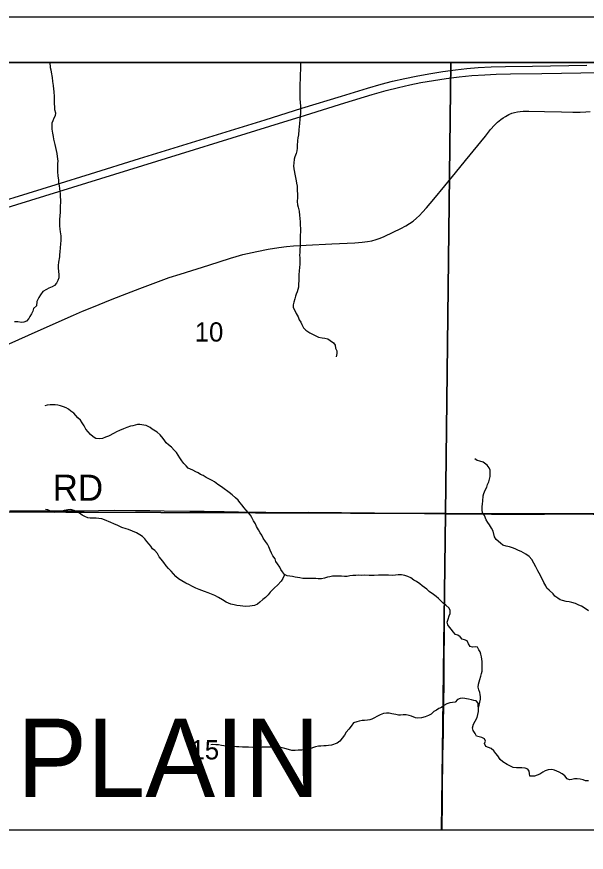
# Model space of a CAD drawing. Extents: x 0 to 34, y 0 to 22.
# Drawn here: x 2.711 to 3.95, y 19.182 to 21 of the extents above; entities that cross this region are included whole.
import ezdxf

# ---------------------------------------------------------------- set-up
doc = ezdxf.new("R2010")
doc.units = 0
for name, color, linetype in [('Default', 7, 'Continuous'), ('GM_X_County_Road', 7, 'Continuous'), ('GM_X_County_Road_Text', 7, 'Continuous'), ('GM_X_Minor_River', 7, 'Continuous'), ('GM_X_Section', 7, 'Continuous'), ('GM_X_Section_Text', 7, 'Continuous'), ('GM_X_State_Route', 7, 'Continuous'), ('GM_X_Township_Road', 7, 'Continuous'), ('GM_X_Township_Text', 7, 'Continuous'), ('GM_X_US_Route', 7, 'Continuous'), ('SH_Data', 7, 'Continuous'), ('SH_Text', 7, 'Continuous')]:
    doc.layers.add(name, color=color, linetype=linetype)

msp = doc.modelspace()

# ---------------------------------------------------------------- linework, layer by layer
at = {"layer": 'Default'}
for points in [[(3.6554, 20.9), (2.6196, 20.9), (2.6102, 19.9231), (3.6434, 19.919)], [(4.655, 20.9), (3.6554, 20.9), (3.6434, 19.919), (4.6576, 19.9182)]]:
    msp.add_lwpolyline(points, close=True, dxfattribs=at)
at = {"layer": 'GM_X_County_Road'}
for points in [[(2.6611, 20.274), (2.7153, 20.298), (2.7578, 20.3168), (2.8346, 20.3505), (2.8542, 20.359), (2.8777, 20.3686), (2.915, 20.3837), (2.9413, 20.3939), (2.9789, 20.4085), (3.0193, 20.424), (3.0312, 20.4284), (3.0426, 20.4323), (3.0665, 20.4397), (3.1285, 20.4596), (3.1761, 20.475), (3.1879, 20.4784), (3.2029, 20.4824), (3.2333, 20.489), (3.2576, 20.494), (3.2813, 20.498), (3.2975, 20.5002), (3.3129, 20.5018), (3.3408, 20.5033), (3.3966, 20.5059), (3.4464, 20.5083), (3.4619, 20.5095), (3.4742, 20.511), (3.4834, 20.5127), (3.4927, 20.515), (3.5015, 20.518), (3.5101, 20.5217), (3.5299, 20.5311), (3.5464, 20.5394), (3.5573, 20.5453), (3.5654, 20.5504), (3.5729, 20.5555), (3.5803, 20.5614), (3.5872, 20.5677), (3.5936, 20.5745), (3.602, 20.5838), (3.6178, 20.6029), (3.6418, 20.6318), (3.6654, 20.6606), (3.6869, 20.6872), (3.7301, 20.7403), (3.7416, 20.7544), (3.75, 20.7638), (3.7565, 20.7704), (3.7636, 20.7763), (3.7688, 20.7799), (3.774, 20.7832), (3.7814, 20.7872), (3.7879, 20.7898), (3.7938, 20.7916), (3.7997, 20.793), (3.8058, 20.7939), (3.812, 20.7944), (3.8243, 20.7945), (3.8585, 20.7938), (3.8957, 20.7927), (3.9204, 20.792), (3.9361, 20.7921), (3.9486, 20.7929), (3.9578, 20.7941)], [(2.6962, 19.9254), (2.7149, 19.9253), (2.7397, 19.9253), (2.7708, 19.9253), (2.805, 19.9251), (2.8578, 19.9251), (2.8889, 19.9257), (2.9231, 19.9261), (2.9697, 19.926), (3.0008, 19.9255), (3.0319, 19.925), (3.0878, 19.9244), (3.1189, 19.924), (3.1622, 19.9237), (3.1936, 19.9231), (3.2245, 19.9223), (3.2525, 19.9218), (3.296, 19.9217), (3.3457, 19.9218), (3.3986, 19.9215), (3.4172, 19.9213), (3.4638, 19.9209), (3.4887, 19.9207), (3.5291, 19.9202), (3.5602, 19.9198), (3.5975, 19.9194), (3.6444, 19.9187)], [(3.6444, 19.9187), (3.6472, 19.9187), (3.6814, 19.9184), (3.7001, 19.9183), (3.7249, 19.9182), (3.7435, 19.918), (3.7715, 19.9177), (3.8026, 19.9179), (3.8585, 19.9179), (3.9207, 19.9181), (3.9393, 19.9181), (3.9642, 19.918), (4.0046, 19.9179), (4.0419, 19.9177), (4.1527, 19.9174)]]:
    msp.add_lwpolyline(points, dxfattribs=at)
at = {"layer": 'GM_X_Minor_River'}
for points in [[(2.7828, 20.9), (2.7839, 20.8897), (2.7851, 20.8847), (2.7859, 20.879), (2.7879, 20.868), (2.789, 20.8589), (2.7902, 20.8505), (2.791, 20.8426), (2.7918, 20.8369), (2.7923, 20.8258), (2.7923, 20.8171), (2.7923, 20.811), (2.7931, 20.803), (2.7935, 20.7981), (2.7955, 20.7909), (2.7944, 20.7844), (2.7921, 20.7791), (2.7895, 20.7737), (2.7876, 20.768), (2.7873, 20.76), (2.7877, 20.7551), (2.7889, 20.7467), (2.7904, 20.7391), (2.7912, 20.7338), (2.7928, 20.7277), (2.7939, 20.7221), (2.797, 20.7091), (2.7982, 20.7023), (2.799, 20.6962), (2.7998, 20.6909), (2.8002, 20.686), (2.7998, 20.6803), (2.7999, 20.67), (2.7996, 20.6635), (2.8007, 20.6529), (2.8016, 20.6449), (2.802, 20.6384), (2.8031, 20.6331), (2.8043, 20.6255), (2.8047, 20.6206), (2.8055, 20.6145), (2.8055, 20.608), (2.806, 20.6016), (2.806, 20.5955), (2.8056, 20.5887), (2.8057, 20.5746), (2.805, 20.567), (2.8043, 20.5586), (2.8044, 20.5453), (2.8051, 20.5377), (2.8059, 20.532), (2.8067, 20.5233), (2.8068, 20.5141), (2.8061, 20.505), (2.8057, 20.4978), (2.805, 20.4879), (2.8043, 20.4829), (2.8043, 20.4776), (2.8017, 20.4662), (2.801, 20.4586), (2.801, 20.4529), (2.8018, 20.4464), (2.8026, 20.4385), (2.8023, 20.432), (2.8008, 20.4259), (2.7978, 20.4206), (2.7929, 20.4152), (2.788, 20.4125), (2.7808, 20.4095), (2.7755, 20.4064), (2.7679, 20.4022), (2.7626, 20.3949), (2.7589, 20.3888), (2.7551, 20.3801), (2.7544, 20.3713), (2.7472, 20.3648), (2.7461, 20.3595), (2.7435, 20.3534), (2.7397, 20.3481), (2.7375, 20.3431), (2.7326, 20.3374), (2.7265, 20.3351), (2.7212, 20.3347), (2.7132, 20.3358), (2.7064, 20.3361)], [(3.3287, 20.9), (3.3285, 20.8979), (3.3278, 20.891), (3.3278, 20.8827), (3.3275, 20.8773), (3.3272, 20.8674), (3.3272, 20.8617), (3.3268, 20.8564), (3.327, 20.823), (3.3275, 20.8119), (3.3279, 20.807), (3.3279, 20.7918), (3.3272, 20.7823), (3.3269, 20.777), (3.3258, 20.7671), (3.3251, 20.761), (3.3247, 20.7541), (3.3236, 20.7427), (3.3225, 20.7366), (3.3218, 20.7309), (3.3207, 20.7191), (3.3208, 20.7142), (3.32, 20.7081), (3.3189, 20.7024), (3.3155, 20.6952), (3.3144, 20.6902), (3.3133, 20.6815), (3.3126, 20.6758), (3.3138, 20.6693), (3.3169, 20.6541), (3.3185, 20.6431), (3.3193, 20.6378), (3.3208, 20.6313), (3.3212, 20.6203), (3.3217, 20.615), (3.3217, 20.607), (3.321, 20.5978), (3.3218, 20.591), (3.3229, 20.5853), (3.3253, 20.5766)], [(3.3253, 20.5766), (3.3261, 20.5675), (3.3269, 20.5618), (3.3273, 20.553), (3.3277, 20.5462), (3.3281, 20.5389), (3.3282, 20.531), (3.3274, 20.5253), (3.3271, 20.5142), (3.3272, 20.5005), (3.3268, 20.4945), (3.3265, 20.4872), (3.3261, 20.4815), (3.3266, 20.4754), (3.327, 20.4678), (3.3266, 20.4606), (3.3259, 20.4553), (3.3252, 20.4465), (3.3245, 20.4393), (3.3245, 20.4317), (3.3242, 20.4268), (3.3238, 20.4173), (3.3239, 20.4116), (3.3209, 20.4017), (3.319, 20.3967), (3.3175, 20.3918), (3.3156, 20.3864), (3.3138, 20.3788), (3.3119, 20.3731), (3.3119, 20.367), (3.3162, 20.3591), (3.3185, 20.3541), (3.3231, 20.3469), (3.3254, 20.3408), (3.3292, 20.3352), (3.3307, 20.3302), (3.3346, 20.323), (3.3399, 20.3177), (3.3483, 20.3124), (3.3673, 20.303), (3.3749, 20.3012), (3.3814, 20.3008), (3.3874, 20.2993), (3.3924, 20.2959), (3.3996, 20.2902), (3.4038, 20.2853), (3.4046, 20.2785), (3.4069, 20.2728), (3.4074, 20.2675), (3.4055, 20.2602)], [(3.2727, 19.8209), (3.2677, 19.8273), (3.265, 19.833), (3.2623, 19.8394), (3.2593, 19.847), (3.2566, 19.8523), (3.2524, 19.858), (3.2467, 19.8656), (3.244, 19.8717), (3.2405, 19.877), (3.2367, 19.8834), (3.2325, 19.891), (3.2302, 19.8967), (3.2263, 19.9035), (3.2221, 19.9104), (3.2191, 19.9153), (3.2099, 19.9266), (3.2049, 19.9323), (3.2011, 19.9376), (3.1961, 19.9433), (3.1923, 19.9482), (3.1866, 19.9535), (3.1797, 19.9596), (3.1729, 19.9649), (3.1592, 19.9747), (3.1542, 19.9785), (3.1485, 19.9819), (3.1409, 19.9883), (3.1359, 19.9906), (3.1302, 19.9936), (3.123, 19.9973), (3.1165, 20.0015), (3.1108, 20.0038), (3.1055, 20.0075), (3.1005, 20.0098), (3.0941, 20.0132), (3.0891, 20.0154), (3.0842, 20.0181), (3.0792, 20.023), (3.0746, 20.0279), (3.0704, 20.0336), (3.0658, 20.0401), (3.062, 20.0461), (3.0586, 20.0518), (3.0532, 20.0571), (3.0475, 20.0635), (3.041, 20.0685), (3.0361, 20.0726), (3.033, 20.0775), (3.0296, 20.0825), (3.0231, 20.0904), (3.0166, 20.0961), (3.0059, 20.1029), (3.001, 20.1063), (2.9926, 20.1104), (2.9873, 20.1116), (2.9785, 20.1127), (2.9736, 20.1126), (2.9634, 20.1099), (2.9585, 20.1091), (2.9505, 20.1064), (2.9433, 20.1037), (2.9346, 20.0995), (2.9282, 20.0968), (2.9232, 20.0942), (2.9104, 20.0876), (2.9043, 20.0853), (2.8975, 20.0826), (2.8918, 20.0815), (2.8831, 20.0826), (2.877, 20.0863), (2.8713, 20.0913), (2.8663, 20.0966), (2.8613, 20.103), (2.8575, 20.1098), (2.8533, 20.1163), (2.8495, 20.122), (2.8441, 20.1276), (2.8395, 20.1326), (2.8353, 20.1375), (2.8285, 20.142), (2.8235, 20.1458), (2.8186, 20.1488), (2.8129, 20.1514), (2.8064, 20.1533), (2.8003, 20.1548), (2.7946, 20.1559), (2.7897, 20.1555), (2.7836, 20.1555), (2.7776, 20.1551), (2.7723, 20.1535)], [(3.8398, 19.8029), (3.8313, 19.8188), (3.8252, 19.8257), (3.8184, 19.8306), (3.8134, 19.8336), (3.8081, 19.8362), (3.8024, 19.8385), (3.7963, 19.8415), (3.7914, 19.8438), (3.7826, 19.8464), (3.7754, 19.8482), (3.7682, 19.8505), (3.7628, 19.8543), (3.7533, 19.8626), (3.7503, 19.8687), (3.7468, 19.8808), (3.7433, 19.8869), (3.7391, 19.8945), (3.7357, 19.8994), (3.7322, 19.9055), (3.7284, 19.9146), (3.7242, 19.9203), (3.723, 19.9271), (3.7233, 19.9339), (3.7241, 19.9404), (3.7248, 19.9461), (3.7255, 19.9575), (3.727, 19.9628), (3.7296, 19.9701), (3.7334, 19.9762), (3.7349, 19.9819), (3.7379, 19.9884), (3.7393, 19.9937), (3.7405, 19.9994), (3.7408, 20.0066), (3.7404, 20.0131), (3.7381, 20.0188), (3.7339, 20.0241), (3.7255, 20.0309), (3.7179, 20.0331), (3.7126, 20.0346), (3.7072, 20.038)], [(3.2939, 19.7864), (3.2937, 19.7856), (3.29, 19.778), (3.2862, 19.7719), (3.2779, 19.7635), (3.2719, 19.7577), (3.267, 19.7528), (3.2624, 19.7478), (3.2575, 19.7425), (3.2523, 19.7363), (3.2462, 19.7318), (3.2394, 19.7264), (3.2345, 19.7218), (3.2281, 19.7187), (3.2231, 19.718), (3.2182, 19.7176), (3.2087, 19.7171), (3.2026, 19.7179), (3.1973, 19.7186), (3.1894, 19.719), (3.1837, 19.7204), (3.1768, 19.7216), (3.1719, 19.7242), (3.1662, 19.7264), (3.1582, 19.7314), (3.1498, 19.7366), (3.1418, 19.7408), (3.1346, 19.7438), (3.1273, 19.7464), (3.1194, 19.7494), (3.1133, 19.7517), (3.108, 19.7539), (3.1007, 19.7569), (3.0916, 19.7611), (3.0866, 19.7637), (3.079, 19.7675), (3.0703, 19.7724), (3.0627, 19.7773), (3.0569, 19.7822), (3.052, 19.7879), (3.047, 19.794), (3.0413, 19.7993), (3.036, 19.8053), (3.031, 19.8125), (3.0249, 19.8197), (3.021, 19.825), (3.0172, 19.8319), (3.0111, 19.8387), (3.0062, 19.8424), (3.0027, 19.8478), (2.9989, 19.8527), (2.9943, 19.8584), (2.9897, 19.8644), (2.9844, 19.8693), (2.9787, 19.8727), (2.9714, 19.8769), (2.9627, 19.8807), (2.9539, 19.884), (2.949, 19.8855), (2.9395, 19.8889), (2.9311, 19.8927), (2.9224, 19.8968), (2.9159, 19.8998), (2.9022, 19.9051), (2.8961, 19.9073), (2.8897, 19.9085), (2.884, 19.9088), (2.8787, 19.9092), (2.8707, 19.9087), (2.8658, 19.9099), (2.8589, 19.9125), (2.8532, 19.9155), (2.8475, 19.9197), (2.841, 19.9231), (2.8357, 19.9257), (2.8281, 19.9276), (2.822, 19.9272), (2.8141, 19.9256), (2.8076, 19.9233), (2.8012, 19.9221), (2.7936, 19.9217), (2.7886, 19.9221), (2.7788, 19.9273), (2.7738, 19.9281)], [(3.7154, 19.4959), (3.7195, 19.5149), (3.7194, 19.5202), (3.719, 19.5252), (3.7179, 19.5301), (3.7159, 19.5358), (3.7144, 19.5411), (3.7151, 19.548), (3.717, 19.5533), (3.7181, 19.5583), (3.72, 19.5651), (3.7218, 19.5708), (3.7229, 19.5761), (3.7229, 19.583), (3.7232, 19.5925), (3.7232, 19.5974), (3.7224, 19.6024), (3.7216, 19.6077), (3.7205, 19.613), (3.7185, 19.618), (3.7162, 19.6229), (3.7128, 19.6282), (3.7079, 19.6289), (3.7022, 19.6285), (3.6972, 19.63), (3.6934, 19.6357), (3.6903, 19.6418), (3.6846, 19.644), (3.6797, 19.6459), (3.6755, 19.6512), (3.6702, 19.6546), (3.6652, 19.6557), (3.6603, 19.6618), (3.6564, 19.6667), (3.6518, 19.672), (3.6488, 19.6769), (3.6469, 19.683), (3.6491, 19.6895), (3.6517, 19.6964), (3.6536, 19.7017), (3.6536, 19.7078), (3.6513, 19.7131), (3.6444, 19.7199), (3.6383, 19.724), (3.6333, 19.729), (3.628, 19.7343), (3.623, 19.7384), (3.6177, 19.7426), (3.6082, 19.7494), (3.6028, 19.7543), (3.5979, 19.7581), (3.5926, 19.7619), (3.5876, 19.766), (3.5807, 19.7709), (3.5747, 19.7743), (3.5682, 19.7789), (3.5613, 19.7819), (3.5552, 19.7845), (3.548, 19.786), (3.5404, 19.786), (3.5347, 19.7852), (3.5283, 19.7844), (3.5196, 19.7847), (3.5127, 19.7847), (3.5055, 19.785), (3.4976, 19.785), (3.4881, 19.7846), (3.4778, 19.7845), (3.4676, 19.7849), (3.4611, 19.7844), (3.455, 19.7848), (3.4486, 19.7844), (3.4418, 19.784), (3.4357, 19.7832), (3.4293, 19.7824), (3.4239, 19.7824), (3.4171, 19.7827), (3.4118, 19.7831), (3.405, 19.7827), (3.3978, 19.7826), (3.3917, 19.7815), (3.3868, 19.7807), (3.3803, 19.7784), (3.3735, 19.7768), (3.3667, 19.7772), (3.3617, 19.7775), (3.3446, 19.7775), (3.3397, 19.7778), (3.3333, 19.7778), (3.3264, 19.7789), (3.3215, 19.7796), (3.3165, 19.7807), (3.3105, 19.7819), (3.2991, 19.7833), (3.2934, 19.7867), (3.2888, 19.792), (3.2857, 19.7973), (3.283, 19.8023), (3.2784, 19.8098), (3.2746, 19.8148), (3.2727, 19.8209)], [(3.9541, 19.7076), (3.9473, 19.7125), (3.9389, 19.7178), (3.9332, 19.7201), (3.9263, 19.7235), (3.9184, 19.7257), (3.9127, 19.7268), (3.9062, 19.7279), (3.8978, 19.7298), (3.8925, 19.7317), (3.8876, 19.7351), (3.8815, 19.7396), (3.8773, 19.7445), (3.8689, 19.7521), (3.8639, 19.757), (3.8616, 19.7619), (3.8574, 19.7692), (3.8513, 19.7817), (3.8474, 19.7893), (3.8444, 19.7942), (3.8398, 19.8029)], [(3.7154, 19.4959), (3.7146, 19.5008), (3.7146, 19.5069), (3.7104, 19.5118), (3.7051, 19.5122), (3.6997, 19.5137), (3.6933, 19.5152), (3.6811, 19.5174), (3.6751, 19.517), (3.6694, 19.5143), (3.6645, 19.509), (3.6588, 19.5082), (3.6531, 19.507), (3.6467, 19.5051), (3.6398, 19.5012), (3.6346, 19.4974), (3.6289, 19.4947), (3.6236, 19.4913), (3.6183, 19.4882), (3.6126, 19.4829), (3.6062, 19.4794), (3.599, 19.4767), (3.591, 19.4748), (3.5834, 19.474), (3.5781, 19.4747), (3.5694, 19.4785), (3.5641, 19.4796), (3.558, 19.4811), (3.5515, 19.4811), (3.5458, 19.4807), (3.5409, 19.4803), (3.5352, 19.4818), (3.5265, 19.4836), (3.5211, 19.4847), (3.5151, 19.4851), (3.5086, 19.4839), (3.5014, 19.4812), (3.4939, 19.4778), (3.4889, 19.4747), (3.4836, 19.472), (3.4787, 19.4705), (3.4738, 19.4697), (3.4673, 19.4685), (3.462, 19.4685), (3.456, 19.4677), (3.4503, 19.4658), (3.4435, 19.4638), (3.4386, 19.4562), (3.4329, 19.4501), (3.4276, 19.4432), (3.4235, 19.4368), (3.419, 19.4307), (3.4137, 19.4238), (3.408, 19.4196), (3.3959, 19.4153), (3.3891, 19.4145), (3.3841, 19.4138), (3.3792, 19.4137), (3.3724, 19.4133), (3.3671, 19.4129), (3.3606, 19.4114), (3.3542, 19.4094), (3.3492, 19.4075), (3.3417, 19.4056), (3.3364, 19.4048), (3.3307, 19.404), (3.3231, 19.404), (3.3166, 19.4036), (3.3094, 19.4039), (3.3018, 19.4054), (3.2938, 19.4077), (3.2851, 19.4099), (3.2756, 19.4106), (3.2619, 19.4105), (3.257, 19.4109), (3.2498, 19.4109), (3.2445, 19.4105), (3.2244, 19.4104), (3.2149, 19.4107), (3.2077, 19.4111), (3.202, 19.411), (3.194, 19.4118), (3.1887, 19.4117), (3.1834, 19.4121), (3.1762, 19.4121), (3.169, 19.4124), (3.1614, 19.4135), (3.1564, 19.4142), (3.1496, 19.4157), (3.1443, 19.4161), (3.1367, 19.4164), (3.1332, 19.416)], [(3.9546, 19.3373), (3.9481, 19.3376), (3.9428, 19.3399), (3.9363, 19.3414), (3.9295, 19.3421), (3.9242, 19.3417), (3.9181, 19.3405), (3.9132, 19.3401), (3.9082, 19.342), (3.9029, 19.3481), (3.8968, 19.3526), (3.8907, 19.3564), (3.8858, 19.3586), (3.8804, 19.3609), (3.8744, 19.362), (3.8664, 19.3616), (3.8599, 19.3593), (3.855, 19.3562), (3.8486, 19.3524), (3.8425, 19.3501), (3.8369, 19.3474), (3.827, 19.3474), (3.8258, 19.3534), (3.8254, 19.3584), (3.8224, 19.3633), (3.8167, 19.3648), (3.8098, 19.3659), (3.8045, 19.3659), (3.7977, 19.3655), (3.7905, 19.3666), (3.7832, 19.37), (3.7775, 19.373), (3.768, 19.379), (3.7623, 19.3843), (3.7573, 19.3923), (3.7531, 19.3972), (3.7485, 19.4025), (3.7424, 19.4082), (3.7367, 19.4104), (3.731, 19.4123), (3.7283, 19.4188), (3.7302, 19.4237), (3.7279, 19.4286), (3.7226, 19.4317), (3.7165, 19.4335), (3.7112, 19.435), (3.7077, 19.4403), (3.7039, 19.4472), (3.7023, 19.4532), (3.7046, 19.4612), (3.7083, 19.4673), (3.7125, 19.4757), (3.7154, 19.4883), (3.7154, 19.4959)]]:
    msp.add_lwpolyline(points, dxfattribs=at)
at = {"layer": 'GM_X_Section'}
for points in [[(3.6346, 19.2311), (3.6434, 19.919), (2.6102, 19.9231), (2.6062, 19.2311)], [(4.6526, 19.2311), (4.6576, 19.9182), (3.6434, 19.919), (3.6346, 19.2311)]]:
    msp.add_lwpolyline(points, close=True, dxfattribs=at)
at = {"layer": 'GM_X_State_Route'}
msp.add_lwpolyline([(5.6507, 20.9), (2.1, 20.9), (2.1, 15.8695)], dxfattribs=at)
at = {"layer": 'GM_X_Township_Road'}
msp.add_lwpolyline([(3.6361, 19.2311), (3.6361, 19.2337), (3.6364, 19.2493), (3.6368, 19.2741), (3.6371, 19.3114), (3.638, 19.3921), (3.6389, 19.4418), (3.6391, 19.4604), (3.6397, 19.5038), (3.64, 19.5193), (3.6403, 19.538), (3.6404, 19.5566), (3.6405, 19.5783), (3.6408, 19.6063), (3.6409, 19.6218), (3.641, 19.6404), (3.6412, 19.6621), (3.6413, 19.6901), (3.6416, 19.7212), (3.642, 19.7709), (3.6422, 19.7957), (3.6429, 19.8391), (3.6432, 19.8577), (3.6438, 19.9012), (3.6442, 19.9136), (3.6444, 19.9187)], dxfattribs=at)
at = {"layer": 'GM_X_US_Route'}
for points in [[(2.6041, 20.5753), (2.797, 20.6352), (2.8713, 20.6581), (2.9781, 20.6913), (3.2512, 20.7759), (3.3314, 20.8007), (3.4175, 20.8273), (3.4741, 20.8444), (3.5039, 20.8531), (3.5279, 20.8594), (3.5551, 20.8658), (3.5794, 20.8709), (3.6069, 20.876), (3.6376, 20.8809), (3.6653, 20.8846), (3.69, 20.8873), (3.7147, 20.8893), (3.7426, 20.8909), (3.7737, 20.8919), (3.8327, 20.8926), (3.9508, 20.8943)], [(2.1, 20.4023), (2.1394, 20.4145), (2.2433, 20.4467), (2.3472, 20.4789), (2.4363, 20.5065), (2.9854, 20.6765), (3.2616, 20.7618), (3.3387, 20.7859), (3.4248, 20.8127), (3.4843, 20.8307), (3.5142, 20.8391), (3.5413, 20.8461), (3.5656, 20.8516), (3.59, 20.8565), (3.6175, 20.8614), (3.6452, 20.8655), (3.673, 20.869), (3.7009, 20.8717), (3.7288, 20.8736), (3.7537, 20.8748), (3.7847, 20.8756), (3.8531, 20.8766), (3.9805, 20.8784)]]:
    msp.add_lwpolyline(points, dxfattribs=at)
at = {"layer": 'SH_Data'}
for p, q in [((2, 21), (9, 21)), ((2.1, 20.9), (8.9, 20.9))]:
    msp.add_line(p, q, dxfattribs=at)
at = {"layer": 'SH_Text'}
msp.add_lwpolyline([(2.4548, 19.2311), (4.6746, 19.2311), (4.6746, 18.514), (2.4548, 18.514)], close=True, dxfattribs=at)

# ---------------------------------------------------------------- texts
at = {"layer": 'GM_X_County_Road_Text'}
msp.add_text('RD', height=0.05682, rotation=0, dxfattribs=at).set_placement((2.7893, 19.9469))
at = {"layer": 'GM_X_Section_Text'}
for s, p in [('10', (3.0981, 20.2932)), ('15', (3.0889, 19.3842))]:
    msp.add_text(s, height=0.04186, rotation=0, dxfattribs=at).set_placement(p)
at = {"layer": 'GM_X_Township_Text'}
msp.add_text('PLAIN', height=0.17045, rotation=0, dxfattribs=at).set_placement((2.7119, 19.3023))

doc.saveas('drawing.dxf')
